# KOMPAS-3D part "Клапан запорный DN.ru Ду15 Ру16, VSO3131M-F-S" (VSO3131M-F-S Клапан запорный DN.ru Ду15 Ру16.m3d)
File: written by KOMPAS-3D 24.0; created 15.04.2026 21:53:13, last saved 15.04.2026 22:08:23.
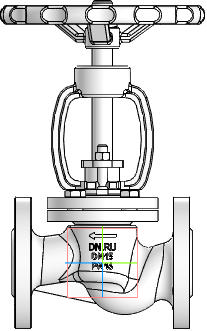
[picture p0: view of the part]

Document properties: Автор: R2D2; Полное имя файла: E:\Работа\Зайцев\VSO3131M-F-S Клапан запорный DN.ru Ду15-100 Ру16\DN15\исходные материалы\VSO3131M-F-S Клапан запорный DN.ru Ду15 Ру16.m3d

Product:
- Part/product: Клапан запорный DN.ru Ду15 Ру16  | designation VSO3131M-F-S
    Масса: 3.45
    Раздел спецификации: Прочие изделия
    Примечание: D090-02946

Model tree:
1. Операция без истории:2

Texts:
  VSO3131M-F-S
